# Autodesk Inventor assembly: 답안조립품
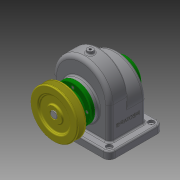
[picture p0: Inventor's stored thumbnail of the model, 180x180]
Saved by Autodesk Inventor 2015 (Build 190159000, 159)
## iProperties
Created: 2017-11
Part Number: 답안조립품
Document SubType Name: Assembly
Designer: 2-PC10
Author: 2-PC10
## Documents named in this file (14)
- C:\Users\2-PC10\Desktop\471108V1020\답안조립품.iam
- C:\Users\2-PC10\Desktop\471108V1020\본체.ipt
- C:\Users\2-PC10\Desktop\471108V1020\축.ipt
- C:\Users\2-PC10\Desktop\471108V1020\스퍼기어.ipt
- C:\Users\2-PC10\Desktop\471108V1020\키 - 6 x 6 x 22.ipt
- C:\Users\2-PC10\Desktop\471108V1020\베어링 6002.ipt
- C:\Users\2-PC10\Desktop\471108V1020\앞커버.ipt
- C:\Users\2-PC10\Desktop\471108V1020\오일 실 15 30 7.ipt
- C:\Users\2-PC10\Desktop\471108V1020\뒤커버.ipt
- C:\Users\2-PC10\Desktop\471108V1020\V-벨트풀리.ipt
- C:\Users\2-PC10\Desktop\471108V1020\키 - 5 x 5 x 18.ipt
- C:\Users\2-PC10\Desktop\471108V1020\멈춤나사 - M4 x 10.ipt
- 멈춤나사 - M4 x 10.ipt
- C:\Users\2-PC10\Desktop\471108V1020\볼트 M3 x 8.ipt
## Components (1 placed, 1 different names)
1. V-벨트풀리:1 — 플러쉬:1
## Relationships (1: Flush 1)
- 플러쉬:1 [Flush]: V-벨트풀리:1
